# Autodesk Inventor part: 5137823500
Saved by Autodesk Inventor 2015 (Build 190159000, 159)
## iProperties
Created: 2020-07
Part Number: 5137823500
Checked By: TraceParts S.A.
Material: Generic
Catalog Web Link: www.traceparts.com
Document SubType Name: Modeling
Designer: TraceParts
Density: 1 g/cm^3
Appearance: Default
Company: TraceParts S.A.
Author: TraceParts
REFERENCE: 5137823500
DESIGN: CVAB/4-6000/450 N D 0,91KW (230V) 50HZ - 5137823500
SUPPLIER: Soler & Palau
TraceParts.PartNumber: 10-14122018-105188
TraceParts.PartTitle: CVAT-N
TraceParts.InstanceId: 10-14122018-105188A6SJHDE3CB852YAUJ4PK6Y1OS
TraceParts.PartStatus: Published
TraceParts.PartVersion: 1.0.4
TRACEPARTS: TRACEPARTS
TraceParts.PartLanguage: en
TraceParts.ClassPath: SOLER_PALAU:10-14122018-105188
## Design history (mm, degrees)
feature "5137823500"
body "Solid1"
